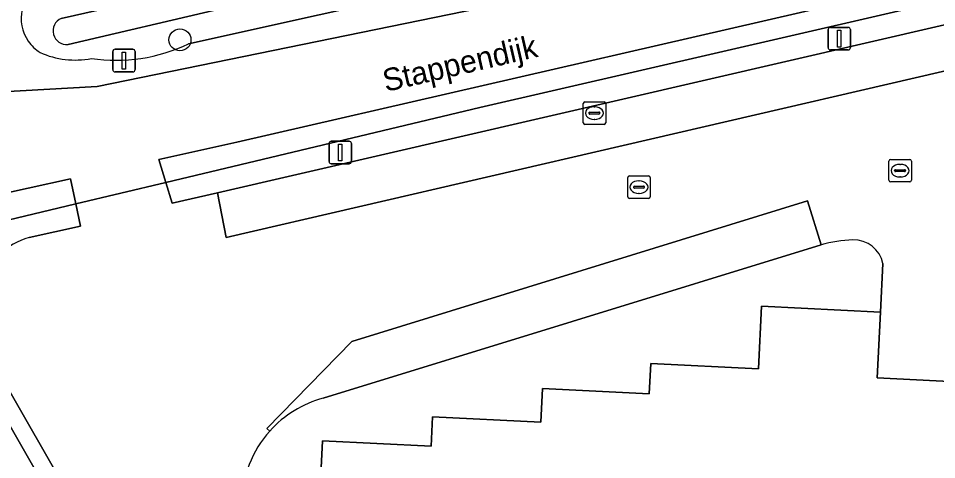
# Model space of a CAD drawing. Extents: x 161090 to 161692, y 379509 to 380907.
# Drawn here: x 161207.93 to 161248.71, y 379714.51 to 379734.11 of the extents above; entities that cross this region are included whole.
import ezdxf

# ---------------------------------------------------------------- set-up
doc = ezdxf.new("R2010")
doc.units = 0
for name, color, linetype in [('IMGEO_Boom', 7, 'Continuous'), ('IMGEO_Erf', 7, 'Continuous'), ('IMGEO_Fietspad_gesloten', 7, 'Continuous'), ('IMGEO_Groenvoorziening', 7, 'Continuous'), ('IMGEO_Hek', 7, 'Continuous'), ('IMGEO_Kolk', 7, 'Continuous'), ('IMGEO_Lichtmast', 7, 'Continuous'), ('IMGEO_Oever', 7, 'Continuous'), ('IMGEO_Openbare_ruimte_label', 7, 'Continuous'), ('IMGEO_Pand', 7, 'Continuous'), ('IMGEO_Parkeervlak_gesloten', 7, 'Continuous'), ('IMGEO_Rijbaan_lokaal_gesloten', 7, 'Continuous'), ('IMGEO_Rioolput', 7, 'Continuous'), ('IMGEO_Verkeersbordpaal', 7, 'Continuous'), ('IMGEO_Waterloop', 7, 'Continuous')]:
    doc.layers.add(name, color=color, linetype=linetype)

msp = doc.modelspace()

# ---------------------------------------------------------------- linework, layer by layer
at = {"layer": 'IMGEO_Boom'}
msp.add_circle((161215.101, 379733.152), 0.489, dxfattribs=at)
at = {"layer": 'IMGEO_Erf'}
for points in [[(161243.578, 379724.047), (161221.468, 379717.239)], [(161221.202, 379710.583), (161221.435, 379715.343), (161226.263, 379715.106), (161226.326, 379716.404), (161231.137, 379716.169), (161231.21, 379717.664), (161235.949, 379717.432), (161236.015, 379718.779), (161240.798, 379718.545), (161240.934, 379721.322), (161246.219, 379721.063), (161246.325, 379723.213)]]:
    msp.add_lwpolyline(points, dxfattribs=at)
for centre, radius, start, end in [((161245.164, 379718.582), 5.691, 91.7141, 106.1855), ((161245.027, 379722.945), 1.326, 11.6765, 91.4146), ((161222.749, 379712.493), 4.916, 105.1074, 138.0537), ((161222.756, 379712.5), 4.917, 138.1622, 179.1438)]:
    msp.add_arc(centre, radius, start, end, dxfattribs=at)
at = {"layer": 'IMGEO_Fietspad_gesloten'}
msp.add_lwpolyline([(161294.533, 379750), (161230.315, 379734.955), (161211.43, 379731.076), (161200.37, 379730.456), (161199.88, 379730.004), (161202.141, 379725.056), (161204.585, 379725.735), (161210.245, 379726.978), (161210.481, 379725.863), (161214.473, 379726.815), (161214.16, 379727.839), (161217.63, 379728.601), (161261.386, 379738.685)], dxfattribs=at)
at = {"layer": 'IMGEO_Groenvoorziening'}
for points in [[(161321.194, 379761.932), (161383.047, 379787.15), (161437.336, 379808.629), (161438.26, 379805.933), (161414.978, 379796.508), (161345.338, 379767.612), (161322.581, 379758.384), (161307.399, 379754.371), (161244.228, 379739.369), (161215.479, 379732.972)], [(161180.807, 379761.477), (161184.615, 379755.126), (161189.385, 379745.645), (161194.335, 379735.113), (161197.105, 379730.453), (161201.159, 379723.634), (161202.937, 379724.063), (161210.481, 379725.863), (161210.245, 379726.978), (161204.585, 379725.735), (161202.141, 379725.056), (161199.88, 379730.004), (161200.37, 379730.456), (161211.43, 379731.076), (161230.315, 379734.955), (161294.533, 379750), (161302.182, 379751.792), (161318.2, 379756.091), (161323.089, 379757.248), (161325.661, 379758.067), (161372.453, 379776.813), (161386.356, 379782.534), (161407.443, 379791.212)], [(161415.916, 379790.022), (161359.784, 379767.053), (161334.748, 379757.161), (161323.449, 379753.122), (161314.492, 379750.449), (161260.228, 379737.49), (161228.423, 379730.143), (161214.473, 379726.815), (161214.755, 379725.892), (161216.77, 379726.358), (161281.548, 379741.341), (161281.646, 379741.364), (161304.908, 379746.911), (161319.404, 379750.447), (161326.887, 379752.243), (161336.716, 379754.602), (161350.416, 379760.36), (161396.996, 379779.937)], [(161208.4, 379724.379), (161210.689, 379724.879), (161210.481, 379725.863), (161202.937, 379724.063), (161224.271, 379686.726), (161228.358, 379679.573), (161235.869, 379665.945), (161239.283, 379660.738), (161256.646, 379660.033), (161297.564, 379658.587), (161325.933, 379655.543), (161331.405, 379655.718), (161331.434, 379654.608), (161331.45, 379654.005), (161340.02, 379653.923), (161369.866, 379654.425), (161387.921, 379654.57), (161405.397, 379654.951), (161418.327, 379655.125), (161449.005, 379655.495), (161461.681, 379655.481), (161461.729, 379656.296)], [(161224.271, 379686.726), (161202.937, 379724.063), (161201.159, 379723.634), (161203.662, 379719.423), (161204.854, 379716.43), (161205.758, 379712.932)], [(161330.98, 379660.087), (161330.998, 379657.104), (161268.498, 379660.484), (161238.653, 379662.022), (161236.659, 379665.622), (161218.401, 379698.575), (161206.424, 379719.47)]]:
    msp.add_lwpolyline(points, dxfattribs=at)
msp.add_lwpolyline([(161214.16, 379727.839), (161214.473, 379726.815), (161228.423, 379730.143), (161260.228, 379737.49), (161314.492, 379750.449), (161323.449, 379753.122), (161334.748, 379757.161), (161359.784, 379767.053), (161415.916, 379790.022), (161415.666, 379790.561), (161387.909, 379779.27), (161368.776, 379771.487), (161333.8, 379757.687), (161330.613, 379756.284), (161320.623, 379753.03), (161308.111, 379750), (161261.386, 379738.685), (161217.63, 379728.601)], close=True, dxfattribs=at)
for centre, radius, start, end in [((161209.849, 379734.112), 1.8, 167.4846, 214.3982), ((161209.848, 379734.116), 1.801, 214.5145, 237.8238), ((161212.257, 379739.735), 7.491, 261.6448, 295.4778), ((161210.452, 379736.058), 3.803, 245.735, 280.8512), ((161209.375, 379721.134), 3.388, 106.7284, 209.4194)]:
    msp.add_arc(centre, radius, start, end, dxfattribs=at)
at = {"layer": 'IMGEO_Hek'}
for points in [[(161415.916, 379790.022), (161359.784, 379767.053), (161334.748, 379757.161), (161323.449, 379753.122), (161314.492, 379750.449), (161260.228, 379737.49), (161228.423, 379730.143), (161214.473, 379726.815)], [(161214.473, 379726.815), (161210.481, 379725.863)], [(161210.481, 379725.863), (161202.937, 379724.063)], [(161224.271, 379686.726), (161202.937, 379724.063)]]:
    msp.add_lwpolyline(points, dxfattribs=at)
at = {"layer": 'IMGEO_Kolk'}
for p, q in [((161233.011, 379729.473), (161233.011, 379730.325)), ((161233.086, 379730.399), (161233.938, 379730.399)), ((161233.499, 379730.179), (161233.524, 379730.179)), ((161234.012, 379730.325), (161234.012, 379729.473)), ((161233.27, 379729.893), (161233.27, 379729.905)), ((161233.708, 379729.856), (161233.31, 379729.856)), ((161233.313, 379729.942), (161233.711, 379729.942)), ((161233.754, 379729.905), (161233.754, 379729.893)), ((161233.938, 379729.399), (161233.086, 379729.399)), ((161233.522, 379729.619), (161233.497, 379729.619))]:
    msp.add_line(p, q, dxfattribs=at)
for points in [[(161233.011, 379729.473), (161233.011, 379730.325)], [(161233.086, 379730.399), (161233.938, 379730.399)], [(161234.012, 379730.325), (161234.012, 379729.473)], [(161233.938, 379729.399), (161233.086, 379729.399)]]:
    msp.add_lwpolyline(points, dxfattribs=at)
for centre, radius, start, end in [((161233.088, 379730.323), 0.0765, 91.552, 178.448), ((161233.088, 379730.323), 0.0765, 91.552, 178.448), ((161233.936, 379730.323), 0.0765, 1.552, 88.448), ((161233.936, 379730.323), 0.0765, 1.552, 88.448), ((161233.31, 379729.902), 0.0403, 85.8775, 175.7526), ((161233.307, 379729.892), 0.0366, 178.938, 274.7102), ((161233.711, 379729.899), 0.043, 264.8664, 352.4533), ((161233.715, 379729.904), 0.0386, 1.7309, 96.639), ((161233.088, 379729.475), 0.0765, 181.552, 268.448), ((161233.088, 379729.475), 0.0765, 181.552, 268.448), ((161233.936, 379729.475), 0.0765, 271.552, 358.448), ((161233.936, 379729.475), 0.0765, 271.552, 358.448)]:
    msp.add_arc(centre, radius, start, end, dxfattribs=at)
for centre, major_axis, ratio, start_param, end_param in [((161233.498, 379729.899), (-0.387, 0.002), 0.722429, 4.712389, 7.853982), ((161233.523, 379729.899), (-0.39, 0.002), 0.717154, 1.570796, 4.712389)]:
    msp.add_ellipse(centre, major_axis=major_axis, ratio=ratio, start_param=start_param, end_param=end_param, dxfattribs=at)
at = {"layer": 'IMGEO_Lichtmast'}
for p, q in [((161243.891, 379732.807), (161243.891, 379733.607)), ((161243.891, 379733.607), (161243.891, 379732.807)), ((161243.991, 379733.707), (161244.781, 379733.707)), ((161244.781, 379733.707), (161243.991, 379733.707)), ((161244.881, 379733.607), (161244.881, 379732.807)), ((161244.881, 379732.807), (161244.881, 379733.607)), ((161244.781, 379732.707), (161243.991, 379732.707)), ((161243.991, 379732.707), (161244.781, 379732.707)), ((161221.725, 379727.75), (161221.725, 379728.55)), ((161221.725, 379728.55), (161221.725, 379727.75)), ((161221.825, 379728.65), (161222.615, 379728.65)), ((161222.615, 379728.65), (161221.825, 379728.65)), ((161222.715, 379728.55), (161222.715, 379727.75)), ((161222.715, 379727.75), (161222.715, 379728.55)), ((161222.615, 379727.65), (161221.825, 379727.65)), ((161221.825, 379727.65), (161222.615, 379727.65))]:
    msp.add_line(p, q, dxfattribs=at)
for points in [[(161244.311, 379733.582), (161244.461, 379733.582), (161244.461, 379732.832), (161244.311, 379732.832), (161244.311, 379733.582)], [(161222.145, 379728.525), (161222.295, 379728.525), (161222.295, 379727.775), (161222.145, 379727.775), (161222.145, 379728.525)]]:
    msp.add_lwpolyline(points, dxfattribs=at)
for centre, start, end in [((161243.991, 379733.607), 90, 180), ((161243.991, 379733.607), 90, 180), ((161244.781, 379733.607), 0, 90), ((161244.781, 379733.607), 360, 90), ((161243.991, 379732.807), 180, 270), ((161243.991, 379732.807), 180, 270), ((161244.781, 379732.807), 270, 0), ((161244.781, 379732.807), 270, 0), ((161221.825, 379728.55), 90, 180), ((161221.825, 379728.55), 90, 180), ((161222.615, 379728.55), 0, 90), ((161222.615, 379728.55), 360, 90), ((161221.825, 379727.75), 180, 270), ((161221.825, 379727.75), 180, 270), ((161222.615, 379727.75), 270, 0), ((161222.615, 379727.75), 270, 0)]:
    msp.add_arc(centre, 0.1, start, end, dxfattribs=at)
at = {"layer": 'IMGEO_Oever'}
for points in [[(161209.828, 379734.106), (161253.524, 379743.962), (161280.711, 379750.533), (161313.565, 379758.418), (161319.274, 379759.897), (161322.067, 379760.718), (161345.722, 379770.082), (161377.919, 379783.264), (161415.988, 379798.829), (161436.933, 379807.33), (161437.303, 379806.344), (161408.802, 379795.092), (161371.225, 379779.322), (161334.181, 379764.414), (161322.108, 379759.712), (161320.444, 379759.342), (161312.949, 379757.494), (161293.093, 379752.607), (161257.077, 379743.942), (161210.131, 379732.941)], [(161215.479, 379732.972), (161244.228, 379739.369), (161307.399, 379754.371)]]:
    msp.add_lwpolyline(points, dxfattribs=at)
for centre, radius, start, end in [((161209.849, 379734.112), 1.8, 167.4846, 214.3982), ((161210.08, 379733.55), 0.611, 114.3313, 274.8264), ((161209.848, 379734.116), 1.801, 214.5145, 237.8238), ((161212.257, 379739.735), 7.491, 261.6448, 295.4778), ((161210.452, 379736.058), 3.803, 245.735, 280.8512)]:
    msp.add_arc(centre, radius, start, end, dxfattribs=at)
at = {"layer": 'IMGEO_Pand'}
msp.add_lwpolyline([(161250.433, 379717.926), (161246.076, 379718.139), (161246.219, 379721.063), (161240.934, 379721.322), (161240.798, 379718.545), (161236.015, 379718.779), (161235.949, 379717.432), (161231.21, 379717.664), (161231.137, 379716.169), (161226.326, 379716.404), (161226.263, 379715.106), (161221.435, 379715.343), (161221.202, 379710.583)], dxfattribs=at)
at = {"layer": 'IMGEO_Parkeervlak_gesloten'}
msp.add_lwpolyline([(161252.424, 379732.547), (161281.952, 379739.475), (161281.548, 379741.341), (161216.77, 379726.358), (161217.161, 379724.368)], close=True, dxfattribs=at)
for points in [[(161243.578, 379724.047), (161242.968, 379725.996), (161222.736, 379719.759), (161218.965, 379715.895), (161219.093, 379715.779)], [(161221.468, 379717.239), (161243.578, 379724.047)]]:
    msp.add_lwpolyline(points, dxfattribs=at)
msp.add_arc((161222.749, 379712.493), 4.916, 105.1074, 138.0537, dxfattribs=at)
at = {"layer": 'IMGEO_Rijbaan_lokaal_gesloten'}
for points in [[(161406.243, 379778.203), (161379.671, 379767.143), (161378.797, 379769.491), (161351.281, 379757.944), (161350.416, 379760.36), (161336.716, 379754.602), (161326.887, 379752.243), (161327.54, 379749.873), (161321.727, 379748.473), (161323.599, 379747.342), (161286.161, 379738.464), (161281.646, 379741.364), (161281.548, 379741.341), (161281.952, 379739.475), (161252.424, 379732.547), (161217.161, 379724.368), (161216.77, 379726.358), (161214.755, 379725.892), (161214.473, 379726.815), (161210.481, 379725.863), (161210.689, 379724.879), (161208.4, 379724.379)], [(161246.325, 379723.213), (161246.219, 379721.063), (161246.076, 379718.139), (161250.433, 379717.926), (161250.668, 379722.709), (161250.811, 379724.811), (161250.867, 379725.627), (161255.194, 379729.467), (161272.678, 379728.697), (161272.452, 379723.904), (161275.323, 379723.746), (161275.212, 379721.444), (161275.139, 379719.939), (161278.336, 379719.783)], [(161219.093, 379715.779), (161218.965, 379715.895), (161222.736, 379719.759), (161242.968, 379725.996), (161243.578, 379724.047)], [(161206.424, 379719.47), (161218.401, 379698.575), (161236.659, 379665.622), (161327.579, 379660.907), (161331.51, 379660.617), (161331.86, 379660.615)]]:
    msp.add_lwpolyline(points, dxfattribs=at)
for centre, radius, start, end in [((161209.375, 379721.134), 3.388, 106.7284, 209.4194), ((161245.164, 379718.582), 5.691, 91.7141, 106.1855), ((161245.027, 379722.945), 1.326, 11.6765, 91.4146), ((161222.756, 379712.5), 4.917, 138.1622, 179.1438)]:
    msp.add_arc(centre, radius, start, end, dxfattribs=at)
at = {"layer": 'IMGEO_Rioolput'}
for p, q in [((161246.587, 379726.917), (161246.587, 379727.769)), ((161246.662, 379727.843), (161247.514, 379727.843)), ((161247.588, 379727.769), (161247.588, 379726.917)), ((161246.846, 379727.337), (161246.846, 379727.349)), ((161246.889, 379727.386), (161247.287, 379727.386)), ((161247.075, 379727.623), (161247.1, 379727.623)), ((161247.33, 379727.349), (161247.33, 379727.337)), ((161234.99, 379726.185), (161234.99, 379727.037)), ((161235.065, 379727.111), (161235.917, 379727.111)), ((161235.991, 379727.037), (161235.991, 379726.185)), ((161247.284, 379727.3), (161246.886, 379727.3)), ((161247.098, 379727.063), (161247.073, 379727.063)), ((161235.249, 379726.605), (161235.249, 379726.617)), ((161235.687, 379726.568), (161235.289, 379726.568)), ((161235.292, 379726.654), (161235.69, 379726.654)), ((161235.478, 379726.891), (161235.503, 379726.891)), ((161235.733, 379726.617), (161235.733, 379726.605)), ((161247.514, 379726.843), (161246.662, 379726.843)), ((161235.917, 379726.111), (161235.065, 379726.111)), ((161235.501, 379726.331), (161235.476, 379726.331))]:
    msp.add_line(p, q, dxfattribs=at)
for points in [[(161246.587, 379726.917), (161246.587, 379727.769)], [(161246.662, 379727.843), (161247.514, 379727.843)], [(161247.588, 379727.769), (161247.588, 379726.917)], [(161234.99, 379726.185), (161234.99, 379727.037)], [(161235.065, 379727.111), (161235.917, 379727.111)], [(161235.991, 379727.037), (161235.991, 379726.185)], [(161247.514, 379726.843), (161246.662, 379726.843)], [(161235.917, 379726.111), (161235.065, 379726.111)]]:
    msp.add_lwpolyline(points, dxfattribs=at)
for centre, radius, start, end in [((161246.664, 379727.767), 0.0765, 91.552, 178.448), ((161246.664, 379727.767), 0.0765, 91.552, 178.448), ((161247.512, 379727.767), 0.0765, 1.552, 88.448), ((161247.512, 379727.767), 0.0765, 1.552, 88.448), ((161246.886, 379727.346), 0.0403, 85.8775, 175.7526), ((161246.883, 379727.336), 0.0366, 178.938, 274.7102), ((161247.287, 379727.343), 0.043, 264.8664, 352.4533), ((161247.291, 379727.348), 0.0386, 1.7309, 96.639), ((161235.067, 379727.035), 0.0765, 91.552, 178.448), ((161235.067, 379727.035), 0.0765, 91.552, 178.448), ((161235.915, 379727.035), 0.0765, 1.552, 88.448), ((161235.915, 379727.035), 0.0765, 1.552, 88.448), ((161246.664, 379726.919), 0.0765, 181.552, 268.448), ((161246.664, 379726.919), 0.0765, 181.552, 268.448), ((161247.512, 379726.919), 0.0765, 271.552, 358.448), ((161247.512, 379726.919), 0.0765, 271.552, 358.448), ((161235.289, 379726.614), 0.0403, 85.8775, 175.7526), ((161235.286, 379726.604), 0.0366, 178.938, 274.7102), ((161235.69, 379726.611), 0.043, 264.8664, 352.4533), ((161235.694, 379726.616), 0.0386, 1.7309, 96.639), ((161235.067, 379726.187), 0.0765, 181.552, 268.448), ((161235.067, 379726.187), 0.0765, 181.552, 268.448), ((161235.915, 379726.187), 0.0765, 271.552, 358.448), ((161235.915, 379726.187), 0.0765, 271.552, 358.448)]:
    msp.add_arc(centre, radius, start, end, dxfattribs=at)
for centre, major_axis, ratio, start_param, end_param in [((161247.074, 379727.343), (-0.387, 0.002), 0.722429, 4.712389, 7.853982), ((161247.099, 379727.343), (-0.39, 0.002), 0.717154, 1.570796, 4.712389), ((161235.477, 379726.611), (-0.387, 0.002), 0.722429, 4.712389, 7.853982), ((161235.502, 379726.611), (-0.39, 0.002), 0.717154, 1.570796, 4.712389)]:
    msp.add_ellipse(centre, major_axis=major_axis, ratio=ratio, start_param=start_param, end_param=end_param, dxfattribs=at)
at = {"layer": 'IMGEO_Verkeersbordpaal'}
for p, q in [((161212.118, 379731.831), (161212.118, 379732.631)), ((161212.118, 379732.631), (161212.118, 379731.831)), ((161212.218, 379732.731), (161213.008, 379732.731)), ((161213.008, 379732.731), (161212.218, 379732.731)), ((161213.108, 379732.631), (161213.108, 379731.831)), ((161213.108, 379731.831), (161213.108, 379732.631)), ((161213.008, 379731.731), (161212.218, 379731.731)), ((161212.218, 379731.731), (161213.008, 379731.731))]:
    msp.add_line(p, q, dxfattribs=at)
msp.add_lwpolyline([(161212.538, 379732.606), (161212.688, 379732.606), (161212.688, 379731.856), (161212.538, 379731.856), (161212.538, 379732.606)], dxfattribs=at)
for centre, start, end in [((161212.218, 379732.631), 90, 180), ((161212.218, 379732.631), 90, 180), ((161213.008, 379732.631), 0, 90), ((161213.008, 379732.631), 360, 90), ((161212.218, 379731.831), 180, 270), ((161212.218, 379731.831), 180, 270), ((161213.008, 379731.831), 270, 0), ((161213.008, 379731.831), 270, 0)]:
    msp.add_arc(centre, 0.1, start, end, dxfattribs=at)
at = {"layer": 'IMGEO_Waterloop'}
for points in [[(161293.093, 379752.607), (161312.949, 379757.494), (161320.444, 379759.342), (161322.108, 379759.712), (161334.181, 379764.414), (161371.225, 379779.322), (161408.802, 379795.092), (161437.303, 379806.344), (161436.933, 379807.33), (161415.988, 379798.829), (161377.919, 379783.264), (161345.722, 379770.082), (161322.067, 379760.718), (161319.274, 379759.897), (161313.565, 379758.418), (161280.711, 379750.533), (161253.524, 379743.962), (161209.828, 379734.106)], [(161210.131, 379732.941), (161257.077, 379743.942), (161293.093, 379752.607)]]:
    msp.add_lwpolyline(points, dxfattribs=at)
msp.add_arc((161210.08, 379733.55), 0.611, 114.3313, 274.8264, dxfattribs=at)

# ---------------------------------------------------------------- texts
at = {"layer": 'IMGEO_Openbare_ruimte_label'}
msp.add_text('Stappendijk', height=1, rotation=13.0075, dxfattribs=at).set_placement((161224.241, 379730.835))

doc.saveas('drawing.dxf')
